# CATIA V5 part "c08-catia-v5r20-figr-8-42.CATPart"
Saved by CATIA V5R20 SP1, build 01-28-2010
Part number: Part1
Bounding box of the stored display mesh (mm): x -75 to 75, y -75 to 75, z 0 to 20
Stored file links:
  D:\v5_r20\psrt_files_downloaded\c08-catia-v5r20-prt\c08-catia-v5r20-figr-8-42.CATPart
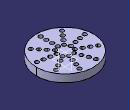
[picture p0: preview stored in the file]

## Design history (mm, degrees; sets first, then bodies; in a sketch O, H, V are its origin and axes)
Body1 (main body)
  Sketch1 on xy-plane, origin (0, 0, 0), H (1, 0, 0), V (0, 1, 0)
    circle A1 centre (0, 0) radius 75
    point P1 (75, 0)
    radius A1 = 75
    coincidence: A1 P1, P1 H
  Pad1: profile Sketch1, direction (0, 0, 1), length 20
  Sketch2 on face of Pad1, origin (0, 0, 20), H (1, 0, 0), V (0, 1, 0)
    circle A1 centre (0, -18.7232) radius 5.1678
    point P1 (0, -18.7232)
    coincidence: P1 V
  Pocket1: profile Sketch2, direction (0, 0, -1), through (limit type 3)
  CircPattern1: of Pocket1, instances 9, angular step 40 {= 360.0*1 deg/CircPattern1.AngularNumber}, circles 4, radial step 15, axis from face of Pad1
